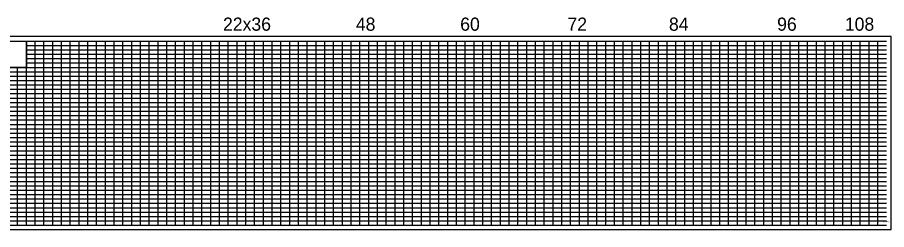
# Model space of a CAD drawing. Extents: x 1873632 to 1926512, y 813126 to 836257.
# Drawn here: x 1889412 to 1894363, y 823042 to 824251 of the extents above; entities that cross this region are included whole.
import ezdxf

# ---------------------------------------------------------------- set-up
doc = ezdxf.new("R2010")
doc.units = 0
for name, color, linetype in [('RD_DDB_StaTX', 7, 'Continuous'), ('RD_PD_WallFill', 7, 'Continuous'), ('RD_SHT_IplotShp', 7, 'Continuous')]:
    doc.layers.add(name, color=color, linetype=linetype)

msp = doc.modelspace()

# ---------------------------------------------------------------- linework, layer by layer
at = {"layer": 'RD_PD_WallFill'}
for p, q in [((1889013.1, 824116.6), (1894363.1, 824116.6)), ((1889013.1, 824116.6), (1890763.1, 824116.6)), ((1889463.1, 823066.6), (1889463.1, 824116.6)), ((1889463.1, 823066.6), (1889463.1, 824116.6)), ((1889513.1, 823066.6), (1889513.1, 824116.6)), ((1889513.1, 823066.6), (1889513.1, 824116.6)), ((1889563.1, 823066.6), (1889563.1, 824116.6)), ((1889563.1, 823066.6), (1889563.1, 824116.6)), ((1889613.1, 823066.6), (1889613.1, 824116.6)), ((1889613.1, 823066.6), (1889613.1, 824116.6)), ((1889663.1, 823066.6), (1889663.1, 824116.6)), ((1889663.1, 823066.6), (1889663.1, 824116.6)), ((1889713.1, 823066.6), (1889713.1, 824116.6)), ((1889713.1, 823066.6), (1889713.1, 824116.6)), ((1889763.1, 823066.6), (1889763.1, 824116.6)), ((1889763.1, 823066.6), (1889763.1, 824116.6)), ((1889813.1, 823066.6), (1889813.1, 824116.6)), ((1889813.1, 823066.6), (1889813.1, 824116.6)), ((1889863.1, 823066.6), (1889863.1, 824116.6)), ((1889863.1, 823066.6), (1889863.1, 824116.6)), ((1889913.1, 823066.6), (1889913.1, 824116.6)), ((1889913.1, 823066.6), (1889913.1, 824116.6)), ((1889963.1, 823066.6), (1889963.1, 824116.6)), ((1889963.1, 823066.6), (1889963.1, 824116.6)), ((1890013.1, 823066.6), (1890013.1, 824116.6)), ((1890013.1, 823066.6), (1890013.1, 824116.6)), ((1890063.1, 823066.6), (1890063.1, 824116.6)), ((1890063.1, 823066.6), (1890063.1, 824116.6)), ((1890113.1, 823066.6), (1890113.1, 824116.6)), ((1890113.1, 823066.6), (1890113.1, 824116.6)), ((1890163.1, 823066.6), (1890163.1, 824116.6)), ((1890163.1, 823066.6), (1890163.1, 824116.6)), ((1890213.1, 823066.6), (1890213.1, 824116.6)), ((1890213.1, 823066.6), (1890213.1, 824116.6)), ((1890263.1, 823066.6), (1890263.1, 824116.6)), ((1890263.1, 823066.6), (1890263.1, 824116.6)), ((1890313.1, 823066.6), (1890313.1, 824116.6)), ((1890313.1, 823066.6), (1890313.1, 824116.6)), ((1890363.1, 823066.6), (1890363.1, 824116.6)), ((1890363.1, 823066.6), (1890363.1, 824116.6)), ((1890413.1, 823066.6), (1890413.1, 824116.6)), ((1890413.1, 823066.6), (1890413.1, 824116.6)), ((1890463.1, 823066.6), (1890463.1, 824116.6)), ((1890463.1, 823066.6), (1890463.1, 824116.6)), ((1890513.1, 823066.6), (1890513.1, 824116.6)), ((1890513.1, 823066.6), (1890513.1, 824116.6)), ((1890563.1, 823066.6), (1890563.1, 824116.6)), ((1890563.1, 823066.6), (1890563.1, 824116.6)), ((1890613.1, 823066.6), (1890613.1, 824116.6)), ((1890613.1, 823066.6), (1890613.1, 824116.6)), ((1890663.1, 823066.6), (1890663.1, 824116.6)), ((1890663.1, 823066.6), (1890663.1, 824116.6)), ((1890713.1, 823066.6), (1890713.1, 824116.6)), ((1890713.1, 823066.6), (1890713.1, 824116.6)), ((1890763.1, 823066.6), (1890763.1, 824116.6)), ((1890763.1, 823066.6), (1890763.1, 824116.6)), ((1890813.1, 823066.6), (1890813.1, 824116.6)), ((1890813.1, 823066.6), (1890813.1, 824116.6)), ((1890863.1, 823066.6), (1890863.1, 824116.6)), ((1890863.1, 823066.6), (1890863.1, 824116.6)), ((1890913.1, 823066.6), (1890913.1, 824116.6)), ((1890913.1, 823066.6), (1890913.1, 824116.6)), ((1890963.1, 823066.6), (1890963.1, 824116.6)), ((1890963.1, 823066.6), (1890963.1, 824116.6)), ((1891013.1, 823066.6), (1891013.1, 824116.6)), ((1891013.1, 823066.6), (1891013.1, 824116.6)), ((1891063.1, 823066.6), (1891063.1, 824116.6)), ((1891063.1, 823066.6), (1891063.1, 824116.6)), ((1891113.1, 823066.6), (1891113.1, 824116.6)), ((1891113.1, 823066.6), (1891113.1, 824116.6)), ((1891163.1, 823066.6), (1891163.1, 824116.6)), ((1891163.1, 823066.6), (1891163.1, 824116.6)), ((1891213.1, 823066.6), (1891213.1, 824116.6)), ((1891213.1, 823066.6), (1891213.1, 824116.6)), ((1891263.1, 823066.6), (1891263.1, 824116.6)), ((1891263.1, 823066.6), (1891263.1, 824116.6)), ((1891313.1, 823066.6), (1891313.1, 824116.6)), ((1891313.1, 823066.6), (1891313.1, 824116.6)), ((1891363.1, 823066.6), (1891363.1, 824116.6)), ((1891363.1, 823066.6), (1891363.1, 824116.6)), ((1891413.1, 823066.6), (1891413.1, 824116.6)), ((1891413.1, 823066.6), (1891413.1, 824116.6)), ((1891463.1, 823066.6), (1891463.1, 824116.6)), ((1891463.1, 823066.6), (1891463.1, 824116.6)), ((1891513.1, 823066.6), (1891513.1, 824116.6)), ((1891513.1, 823066.6), (1891513.1, 824116.6)), ((1891563.1, 823066.6), (1891563.1, 824116.6)), ((1891563.1, 823066.6), (1891563.1, 824116.6)), ((1891613.1, 823066.6), (1891613.1, 824116.6)), ((1891613.1, 823066.6), (1891613.1, 824116.6)), ((1891663.1, 823066.6), (1891663.1, 824116.6)), ((1891663.1, 823066.6), (1891663.1, 824116.6)), ((1891713.1, 823066.6), (1891713.1, 824116.6)), ((1891713.1, 823066.6), (1891713.1, 824116.6)), ((1891763.1, 823066.6), (1891763.1, 824116.6)), ((1891763.1, 823066.6), (1891763.1, 824116.6)), ((1891813.1, 823066.6), (1891813.1, 824116.6)), ((1891813.1, 823066.6), (1891813.1, 824116.6)), ((1891863.1, 823066.6), (1891863.1, 824116.6)), ((1891863.1, 823066.6), (1891863.1, 824116.6)), ((1891913.1, 823066.6), (1891913.1, 824116.6)), ((1891913.1, 823066.6), (1891913.1, 824116.6)), ((1891963.1, 823066.6), (1891963.1, 824116.6)), ((1891963.1, 823066.6), (1891963.1, 824116.6)), ((1892013.1, 823066.6), (1892013.1, 824116.6)), ((1892013.1, 823066.6), (1892013.1, 824116.6)), ((1892063.1, 823066.6), (1892063.1, 824116.6)), ((1892063.1, 823066.6), (1892063.1, 824116.6)), ((1892113.1, 823066.6), (1892113.1, 824116.6)), ((1892113.1, 823066.6), (1892113.1, 824116.6)), ((1892163.1, 823066.6), (1892163.1, 824116.6)), ((1892163.1, 823066.6), (1892163.1, 824116.6)), ((1892213.1, 823066.6), (1892213.1, 824116.6)), ((1892213.1, 823066.6), (1892213.1, 824116.6)), ((1892263.1, 823066.6), (1892263.1, 824116.6)), ((1892263.1, 823066.6), (1892263.1, 824116.6)), ((1892313.1, 823066.6), (1892313.1, 824116.6)), ((1892313.1, 823066.6), (1892313.1, 824116.6)), ((1892363.1, 823066.6), (1892363.1, 824116.6)), ((1892363.1, 823066.6), (1892363.1, 824116.6)), ((1892413.1, 823066.6), (1892413.1, 824116.6)), ((1892413.1, 823066.6), (1892413.1, 824116.6)), ((1892463.1, 823066.6), (1892463.1, 824116.6)), ((1892463.1, 823066.6), (1892463.1, 824116.6)), ((1892513.1, 823066.6), (1892513.1, 824116.6)), ((1892513.1, 823066.6), (1892513.1, 824116.6)), ((1892563.1, 823066.6), (1892563.1, 824116.6)), ((1892563.1, 823066.6), (1892563.1, 824116.6)), ((1892613.1, 823066.6), (1892613.1, 824116.6)), ((1892613.1, 823066.6), (1892613.1, 824116.6)), ((1892663.1, 823066.6), (1892663.1, 824116.6)), ((1892663.1, 823066.6), (1892663.1, 824116.6)), ((1892713.1, 823066.6), (1892713.1, 824116.6)), ((1892713.1, 823066.6), (1892713.1, 824116.6)), ((1892763.1, 823066.6), (1892763.1, 824116.6)), ((1892763.1, 823066.6), (1892763.1, 824116.6)), ((1892813.1, 823066.6), (1892813.1, 824116.6)), ((1892813.1, 823066.6), (1892813.1, 824116.6)), ((1892863.1, 823066.6), (1892863.1, 824116.6)), ((1892863.1, 823066.6), (1892863.1, 824116.6)), ((1892913.1, 823066.6), (1892913.1, 824116.6)), ((1892913.1, 823066.6), (1892913.1, 824116.6)), ((1892963.1, 823066.6), (1892963.1, 824116.6)), ((1892963.1, 823066.6), (1892963.1, 824116.6)), ((1893013.1, 823066.6), (1893013.1, 824116.6)), ((1893013.1, 823066.6), (1893013.1, 824116.6)), ((1893063.1, 823066.6), (1893063.1, 824116.6)), ((1893063.1, 823066.6), (1893063.1, 824116.6)), ((1893113.1, 823066.6), (1893113.1, 824116.6)), ((1893113.1, 823066.6), (1893113.1, 824116.6)), ((1893163.1, 823066.6), (1893163.1, 824116.6)), ((1893163.1, 823066.6), (1893163.1, 824116.6)), ((1893213.1, 823066.6), (1893213.1, 824116.6)), ((1893213.1, 823066.6), (1893213.1, 824116.6)), ((1893263.1, 823066.6), (1893263.1, 824116.6)), ((1893263.1, 823066.6), (1893263.1, 824116.6)), ((1893313.1, 823066.6), (1893313.1, 824116.6)), ((1893313.1, 823066.6), (1893313.1, 824116.6)), ((1893363.1, 823066.6), (1893363.1, 824116.6)), ((1893363.1, 823066.6), (1893363.1, 824116.6)), ((1893413.1, 823066.6), (1893413.1, 824116.6)), ((1893413.1, 823066.6), (1893413.1, 824116.6)), ((1893463.1, 823066.6), (1893463.1, 824116.6)), ((1893463.1, 823066.6), (1893463.1, 824116.6)), ((1893513.1, 823066.6), (1893513.1, 824116.6)), ((1893513.1, 823066.6), (1893513.1, 824116.6)), ((1893563.1, 823066.6), (1893563.1, 824116.6)), ((1893563.1, 823066.6), (1893563.1, 824116.6)), ((1893613.1, 823066.6), (1893613.1, 824116.6)), ((1893613.1, 823066.6), (1893613.1, 824116.6)), ((1893663.1, 823066.6), (1893663.1, 824116.6)), ((1893663.1, 823066.6), (1893663.1, 824116.6)), ((1893713.1, 823066.6), (1893713.1, 824116.6)), ((1893713.1, 823066.6), (1893713.1, 824116.6)), ((1893763.1, 823066.6), (1893763.1, 824116.6)), ((1893763.1, 823066.6), (1893763.1, 824116.6)), ((1893813.1, 823066.6), (1893813.1, 824116.6)), ((1893813.1, 823066.6), (1893813.1, 824116.6)), ((1893863.1, 823066.6), (1893863.1, 824116.6)), ((1893863.1, 823066.6), (1893863.1, 824116.6)), ((1893913.1, 823066.6), (1893913.1, 824116.6)), ((1893913.1, 823066.6), (1893913.1, 824116.6)), ((1893963.1, 823066.6), (1893963.1, 824116.6)), ((1893963.1, 823066.6), (1893963.1, 824116.6)), ((1894013.1, 823066.6), (1894013.1, 824116.6)), ((1894013.1, 823066.6), (1894013.1, 824116.6)), ((1894063.1, 823066.6), (1894063.1, 824116.6)), ((1894063.1, 823066.6), (1894063.1, 824116.6)), ((1894113.1, 823066.6), (1894113.1, 824116.6)), ((1894113.1, 823066.6), (1894113.1, 824116.6)), ((1894163.1, 823066.6), (1894163.1, 824116.6)), ((1894163.1, 823066.6), (1894163.1, 824116.6)), ((1894213.1, 823066.6), (1894213.1, 824116.6)), ((1894213.1, 823066.6), (1894213.1, 824116.6)), ((1894263.1, 823066.6), (1894263.1, 824116.6)), ((1894263.1, 823066.6), (1894263.1, 824116.6)), ((1894313.1, 823066.6), (1894313.1, 824116.6)), ((1894313.1, 823066.6), (1894313.1, 824116.6)), ((1889463.1, 824091.6), (1894363.1, 824091.6)), ((1889463.1, 824091.6), (1894363.1, 824091.6)), ((1889463.1, 824066.6), (1894363.1, 824066.6)), ((1889463.1, 824041.6), (1894363.1, 824041.6)), ((1889463.1, 824016.6), (1894363.1, 824016.6)), ((1889013.1, 823966.6), (1894363.1, 823966.6)), ((1889413.1, 823066.6), (1889413.1, 823966.6)), ((1889413.1, 823066.6), (1889413.1, 823966.6)), ((1889463.1, 823991.6), (1894363.1, 823991.6)), ((1889013.1, 823941.6), (1894363.1, 823941.6)), ((1889013.1, 823916.6), (1894363.1, 823916.6)), ((1889013.1, 823891.6), (1894363.1, 823891.6)), ((1889013.1, 823866.6), (1894363.1, 823866.6)), ((1889013.1, 823841.6), (1894363.1, 823841.6)), ((1889013.1, 823816.6), (1894363.1, 823816.6)), ((1889013.1, 823791.6), (1894363.1, 823791.6)), ((1889013.1, 823766.6), (1894363.1, 823766.6)), ((1889013.1, 823741.6), (1894363.1, 823741.6)), ((1889013.1, 823716.6), (1894363.1, 823716.6)), ((1889013.1, 823691.6), (1894363.1, 823691.6)), ((1889013.1, 823666.6), (1894363.1, 823666.6)), ((1889013.1, 823641.6), (1894363.1, 823641.6)), ((1889013.1, 823616.6), (1894363.1, 823616.6)), ((1889013.1, 823591.6), (1894363.1, 823591.6)), ((1889013.1, 823566.6), (1894363.1, 823566.6)), ((1889013.1, 823541.6), (1894363.1, 823541.6)), ((1889013.1, 823516.6), (1894363.1, 823516.6)), ((1889013.1, 823491.6), (1894363.1, 823491.6)), ((1889013.1, 823466.6), (1894363.1, 823466.6)), ((1889013.1, 823441.6), (1894363.1, 823441.6)), ((1889013.1, 823416.6), (1894363.1, 823416.6)), ((1889013.1, 823391.6), (1894363.1, 823391.6)), ((1889013.1, 823366.6), (1894363.1, 823366.6)), ((1889013.1, 823341.6), (1894363.1, 823341.6)), ((1889013.1, 823316.6), (1894363.1, 823316.6)), ((1889013.1, 823291.6), (1894363.1, 823291.6)), ((1889013.1, 823266.6), (1894363.1, 823266.6)), ((1889013.1, 823241.6), (1894363.1, 823241.6)), ((1889013.1, 823216.6), (1894363.1, 823216.6)), ((1889013.1, 823191.6), (1894363.1, 823191.6)), ((1889013.1, 823166.6), (1894363.1, 823166.6)), ((1889013.1, 823141.6), (1894363.1, 823141.6)), ((1889013.1, 823116.6), (1894363.1, 823116.6)), ((1889013.1, 823091.6), (1894363.1, 823091.6)), ((1889013.1, 823066.6), (1894363.1, 823066.6)), ((1889013.1, 823066.6), (1894363.1, 823066.6))]:
    msp.add_line(p, q, dxfattribs=at)
msp.add_lwpolyline([(1889063.1, 824116.6), (1889463.1, 824116.6), (1889463.1, 823966.6), (1889063.1, 823966.6)], close=True, dxfattribs=at)
msp.add_lwpolyline([(1889063.1, 824116.6), (1889463.1, 824116.6), (1889463.1, 823966.6), (1889063.1, 823966.6)], close=True, dxfattribs=at)
msp.add_lwpolyline([(1889063.1, 824116.6), (1889463.1, 824116.6), (1889463.1, 823966.6), (1889063.1, 823966.6)], close=True, dxfattribs=at)
msp.add_lwpolyline([(1889063.1, 824116.6), (1889463.1, 824116.6), (1889463.1, 823966.6), (1889063.1, 823966.6)], close=True, dxfattribs=at)
at = {"layer": 'RD_SHT_IplotShp'}
msp.add_lwpolyline([(1888988.1, 823041.6), (1894388.1, 823041.6), (1894388.1, 824141.6), (1888988.1, 824141.6)], close=True, dxfattribs=at)

# ---------------------------------------------------------------- texts
at = {"layer": 'RD_DDB_StaTX'}
msp.add_text('170+00', height=8, dxfattribs=at).set_placement((1894342.2, 823082.6))
at = {"layer": 'RD_PD_WallFill'}
for s, p in [('22x36', (1890583.2, 824175.3)), ('22x36', (1890583.2, 824175.3)), ('48', (1891339.8, 824175.3)), ('48', (1891339.8, 824175.3)), ('60', (1891934.2, 824175.3)), ('60', (1891934.2, 824175.3)), ('72', (1892544.9, 824175.3)), ('72', (1892544.9, 824175.3)), ('84', (1893123.2, 824175.3)), ('84', (1893123.2, 824175.3)), ('96', (1893739.2, 824175.3)), ('96', (1893739.2, 824175.3)), ('108', (1894125, 824175.3))]:
    msp.add_text(s, height=75, dxfattribs=at).set_placement(p)

doc.saveas('drawing.dxf')
